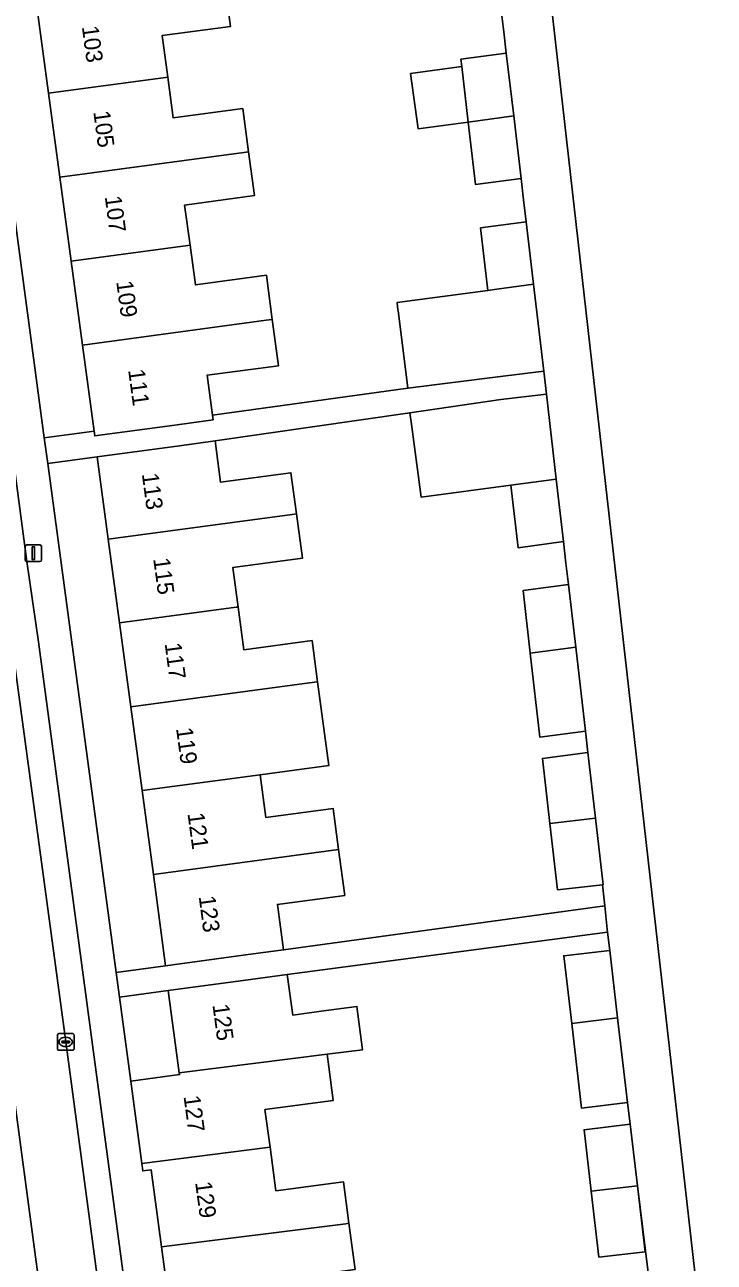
# Model space of a CAD drawing. Extents: x 163147 to 163550, y 380933 to 381639.
# Drawn here: x 163508.4 to 163549.9, y 381142.9 to 381217.3 of the extents above; entities that cross this region are included whole.
import ezdxf

# ---------------------------------------------------------------- set-up
doc = ezdxf.new("R2010")
doc.units = 0
for name, color, linetype in [('IMGEO_Erf', 7, 'Continuous'), ('IMGEO_Kolk', 7, 'Continuous'), ('IMGEO_Lichtmast', 7, 'Continuous'), ('IMGEO_Pand', 7, 'Continuous'), ('IMGEO_Pand_nummerreeks', 7, 'Continuous'), ('IMGEO_Parkeervlak_open', 7, 'Continuous'), ('IMGEO_Rijbaan_lokaal_open', 7, 'Continuous'), ('IMGEO_Voetpad_open', 7, 'Continuous')]:
    doc.layers.add(name, color=color, linetype=linetype)

msp = doc.modelspace()

# ---------------------------------------------------------------- linework, layer by layer
at = {"layer": 'IMGEO_Erf'}
for points in [[(163509.837, 381213.166), (163509.156, 381218.215), (163508.481, 381223.221), (163505.501, 381222.821), (163509.584, 381192.438), (163512.578, 381192.84), (163511.88, 381198.018), (163511.199, 381203.067), (163510.518, 381208.118)], [(163538.808, 381179.487), (163538.372, 381183.255), (163541.103, 381183.62), (163540.955, 381184.902), (163540.805, 381186.2), (163538.074, 381185.835), (163537.64, 381189.595), (163532.254, 381188.873), (163531.647, 381193.406), (163531.613, 381193.661), (163531.573, 381193.955), (163519.853, 381192.255), (163520.187, 381189.773), (163524.411, 381190.341), (163524.744, 381187.867), (163525.102, 381185.202), (163520.915, 381184.639), (163521.234, 381182.265), (163521.58, 381179.696), (163525.684, 381180.248), (163526.017, 381177.774), (163526.694, 381172.735), (163522.559, 381172.179), (163522.904, 381169.614), (163526.948, 381170.157), (163527.281, 381167.679), (163527.652, 381164.926), (163523.606, 381164.381), (163523.974, 381161.65), (163543.281, 381164.294), (163543.148, 381165.564), (163540.453, 381165.253), (163539.991, 381169.249), (163539.54, 381173.152), (163542.27, 381173.518), (163542.122, 381174.799), (163539.392, 381174.433)], [(163514.787, 381176.271), (163514.109, 381181.312), (163513.431, 381186.352), (163512.765, 381191.302), (163509.79, 381190.902), (163513.902, 381160.296), (163516.882, 381160.696), (163516.143, 381166.188), (163515.465, 381171.229)], [(163517.036, 381159.196), (163514.103, 381158.802), (163514.782, 381153.75), (163517.716, 381154.144), (163517.7, 381154.26)]]:
    msp.add_lwpolyline(points, close=True, dxfattribs=at)
for points in [[(163520.445, 381219.741), (163520.789, 381217.19), (163516.668, 381216.634), (163517.005, 381214.135), (163517.337, 381211.678), (163521.516, 381212.241), (163521.865, 381209.651), (163522.222, 381207.008), (163518.021, 381206.442), (163518.346, 381204.034), (163518.668, 381201.643), (163522.936, 381202.219), (163523.295, 381199.561), (163523.67, 381196.782), (163519.371, 381196.202), (163519.695, 381193.797), (163531.445, 381195.429), (163530.877, 381199.938), (163530.828, 381200.329), (163530.797, 381200.575), (163536.256, 381201.313), (163535.818, 381205.07), (163538.558, 381205.441), (163538.404, 381206.748), (163538.252, 381208.042), (163535.514, 381207.671), (163535.075, 381211.436), (163532.062, 381211.028), (163531.612, 381214.354), (163534.686, 381214.77), (163534.635, 381215.209), (163537.365, 381215.579), (163537.213, 381216.868), (163537.063, 381218.145)], [(163545.895, 381142.238), (163545.254, 381147.457), (163545.717, 381143.486), (163542.939, 381143.162), (163542.476, 381147.133), (163542.045, 381150.828), (163544.815, 381151.177), (163544.662, 381152.474), (163541.894, 381152.126), (163541.3, 381157.22), (163540.824, 381161.297), (163543.582, 381161.618), (163543.453, 381162.715), (163524.194, 381160.159), (163524.521, 381157.725), (163526.242, 381157.957), (163528.378, 381158.245), (163528.728, 381155.643), (163526.589, 381155.375), (163526.692, 381154.612), (163526.963, 381152.596), (163522.854, 381152.043), (163523.159, 381149.777), (163523.511, 381147.159), (163527.567, 381147.704), (163527.903, 381145.205), (163528.276, 381142.433)]]:
    msp.add_lwpolyline(points, dxfattribs=at)
at = {"layer": 'IMGEO_Kolk'}
for p, q in [((163510.371, 381155.684), (163510.371, 381156.536)), ((163510.446, 381156.61), (163511.298, 381156.61)), ((163510.63, 381156.104), (163510.63, 381156.116)), ((163511.068, 381156.067), (163510.67, 381156.067)), ((163510.673, 381156.153), (163511.071, 381156.153)), ((163510.859, 381156.39), (163510.884, 381156.39)), ((163511.114, 381156.116), (163511.114, 381156.104)), ((163511.372, 381156.536), (163511.372, 381155.684)), ((163511.298, 381155.61), (163510.446, 381155.61)), ((163510.882, 381155.83), (163510.857, 381155.83))]:
    msp.add_line(p, q, dxfattribs=at)
for points in [[(163510.371, 381155.684), (163510.371, 381156.536)], [(163510.446, 381156.61), (163511.298, 381156.61)], [(163511.372, 381156.536), (163511.372, 381155.684)], [(163511.298, 381155.61), (163510.446, 381155.61)]]:
    msp.add_lwpolyline(points, dxfattribs=at)
for centre, radius, start, end in [((163510.448, 381156.534), 0.0765, 91.55205, 178.44795), ((163510.448, 381156.534), 0.0765, 91.55205, 178.44795), ((163510.67, 381156.113), 0.0403, 85.87752, 175.75265), ((163510.667, 381156.103), 0.0366, 178.93798, 274.71019), ((163511.071, 381156.11), 0.043, 264.86636, 352.45326), ((163511.075, 381156.115), 0.0386, 1.73085, 96.63898), ((163511.296, 381156.534), 0.0765, 1.55205, 88.44795), ((163511.296, 381156.534), 0.0765, 1.55205, 88.44795), ((163510.448, 381155.686), 0.0765, 181.55205, 268.44795), ((163510.448, 381155.686), 0.0765, 181.55205, 268.44795), ((163511.296, 381155.686), 0.0765, 271.55205, 358.44795), ((163511.296, 381155.686), 0.0765, 271.55205, 358.44795)]:
    msp.add_arc(centre, radius, start, end, dxfattribs=at)
for centre, major_axis, ratio, start_param, end_param in [((163510.858, 381156.11), (-0.387, 0.002), 0.722429, 4.712389, 7.853982), ((163510.883, 381156.11), (-0.39, 0.002), 0.717154, 1.570796, 4.712389)]:
    msp.add_ellipse(centre, major_axis=major_axis, ratio=ratio, start_param=start_param, end_param=end_param, dxfattribs=at)
at = {"layer": 'IMGEO_Lichtmast'}
for p, q in [((163508.428, 381185.106), (163508.428, 381185.906)), ((163508.428, 381185.906), (163508.428, 381185.106)), ((163508.528, 381186.006), (163509.318, 381186.006)), ((163509.318, 381186.006), (163508.528, 381186.006)), ((163509.418, 381185.906), (163509.418, 381185.106)), ((163509.418, 381185.106), (163509.418, 381185.906)), ((163509.318, 381185.006), (163508.528, 381185.006)), ((163508.528, 381185.006), (163509.318, 381185.006))]:
    msp.add_line(p, q, dxfattribs=at)
msp.add_lwpolyline([(163508.848, 381185.881), (163508.998, 381185.881), (163508.998, 381185.131), (163508.848, 381185.131), (163508.848, 381185.881)], dxfattribs=at)
for centre, start, end in [((163508.528, 381185.906), 90, 180), ((163508.528, 381185.906), 90, 180), ((163509.318, 381185.906), 0, 90), ((163509.318, 381185.906), 360, 90), ((163508.528, 381185.106), 180, 270), ((163508.528, 381185.106), 180, 270), ((163509.318, 381185.106), 270, 0), ((163509.318, 381185.106), 270, 0)]:
    msp.add_arc(centre, 0.1, start, end, dxfattribs=at)
at = {"layer": 'IMGEO_Pand'}
for points in [[(163517.005, 381214.135), (163516.668, 381216.634), (163520.789, 381217.19), (163520.445, 381219.741), (163520.224, 381219.711), (163509.156, 381218.215), (163509.837, 381213.166), (163516.87, 381214.117)], [(163537.365, 381215.579), (163534.635, 381215.209), (163534.686, 381214.77), (163535.075, 381211.436), (163537.809, 381211.805)], [(163534.686, 381214.77), (163531.612, 381214.354), (163532.062, 381211.028), (163535.075, 381211.436)], [(163510.518, 381208.118), (163521.575, 381209.612), (163521.865, 381209.651), (163521.516, 381212.241), (163517.337, 381211.678), (163517.005, 381214.135), (163516.87, 381214.117), (163509.837, 381213.166)], [(163537.809, 381211.805), (163535.075, 381211.436), (163535.514, 381207.671), (163538.252, 381208.042)], [(163510.518, 381208.118), (163511.199, 381203.067), (163518.221, 381204.017), (163518.346, 381204.034), (163518.021, 381206.442), (163522.222, 381207.008), (163521.865, 381209.651), (163521.575, 381209.612)], [(163538.558, 381205.441), (163535.818, 381205.07), (163536.256, 381201.313), (163536.8, 381201.387), (163539, 381201.684)], [(163511.88, 381198.018), (163522.925, 381199.511), (163523.295, 381199.561), (163522.936, 381202.219), (163518.668, 381201.643), (163518.346, 381204.034), (163518.221, 381204.017), (163511.199, 381203.067)], [(163539, 381201.684), (163536.8, 381201.387), (163536.256, 381201.313), (163530.797, 381200.575), (163530.828, 381200.329), (163530.877, 381199.938), (163531.445, 381195.429), (163536.862, 381196.112), (163539.615, 381196.459)], [(163519.371, 381196.202), (163523.67, 381196.782), (163523.295, 381199.561), (163522.925, 381199.511), (163511.88, 381198.018), (163512.578, 381192.84), (163512.616, 381192.558), (163517.572, 381193.227), (163519.733, 381193.518), (163519.695, 381193.797)], [(163539.78, 381195.068), (163537.044, 381194.749), (163531.573, 381193.955), (163531.613, 381193.661), (163531.647, 381193.406), (163532.254, 381188.873), (163537.64, 381189.595), (163540.37, 381189.961)], [(163524.744, 381187.867), (163524.411, 381190.341), (163520.187, 381189.773), (163519.853, 381192.255), (163517.721, 381191.968), (163512.765, 381191.302), (163513.431, 381186.352), (163524.487, 381187.833)], [(163540.37, 381189.961), (163537.64, 381189.595), (163538.074, 381185.835), (163540.805, 381186.2)], [(163521.234, 381182.265), (163520.915, 381184.639), (163525.102, 381185.202), (163524.744, 381187.867), (163524.487, 381187.833), (163513.431, 381186.352), (163514.109, 381181.312), (163521.131, 381182.251)], [(163541.103, 381183.62), (163538.372, 381183.255), (163538.808, 381179.487), (163541.538, 381179.852)], [(163521.234, 381182.265), (163521.131, 381182.251), (163514.109, 381181.312), (163514.787, 381176.271), (163525.835, 381177.75), (163526.017, 381177.774), (163525.684, 381180.248), (163521.58, 381179.696)], [(163538.808, 381179.487), (163539.392, 381174.433), (163542.122, 381174.799), (163541.538, 381179.852)], [(163526.017, 381177.774), (163525.835, 381177.75), (163514.787, 381176.271), (163515.465, 381171.229), (163522.559, 381172.179), (163526.694, 381172.735)], [(163542.27, 381173.518), (163539.54, 381173.152), (163539.991, 381169.249), (163542.727, 381169.568)], [(163522.559, 381172.179), (163515.465, 381171.229), (163516.143, 381166.188), (163527.281, 381167.679), (163526.948, 381170.157), (163522.904, 381169.614)], [(163542.727, 381169.568), (163539.991, 381169.249), (163540.453, 381165.253), (163543.148, 381165.564), (163543.189, 381165.569)], [(163527.281, 381167.679), (163516.143, 381166.188), (163516.882, 381160.696), (163521.838, 381161.363), (163523.974, 381161.65), (163523.606, 381164.381), (163527.652, 381164.926)], [(163543.582, 381161.618), (163540.824, 381161.297), (163541.3, 381157.22), (163544.061, 381157.566)], [(163524.194, 381160.159), (163521.992, 381159.863), (163517.036, 381159.196), (163517.7, 381154.26), (163526.589, 381155.375), (163528.728, 381155.643), (163528.378, 381158.245), (163526.242, 381157.957), (163524.521, 381157.725)], [(163544.061, 381157.566), (163541.3, 381157.22), (163541.894, 381152.126), (163544.662, 381152.474)], [(163526.692, 381154.612), (163526.589, 381155.375), (163517.7, 381154.26), (163517.716, 381154.144), (163514.782, 381153.75), (163515.446, 381148.81), (163523.014, 381149.759), (163523.159, 381149.777), (163522.854, 381152.043), (163526.963, 381152.596)], [(163544.815, 381151.177), (163542.045, 381150.828), (163542.476, 381147.133), (163545.254, 381147.457)], [(163515.446, 381148.81), (163515.507, 381148.36), (163516.006, 381148.427), (163516.63, 381143.791), (163527.724, 381145.183), (163527.903, 381145.205), (163527.567, 381147.704), (163523.511, 381147.159), (163523.159, 381149.777), (163523.014, 381149.759)], [(163545.254, 381147.457), (163542.476, 381147.133), (163542.939, 381143.162), (163545.717, 381143.486)], [(163517.313, 381138.711), (163524.359, 381139.594), (163524.515, 381139.614), (163524.21, 381141.886), (163528.276, 381142.433), (163527.903, 381145.205), (163527.724, 381145.183), (163516.63, 381143.791)]]:
    msp.add_lwpolyline(points, close=True, dxfattribs=at)
at = {"layer": 'IMGEO_Parkeervlak_open'}
for points in [[(163503.796, 381208.674), (163504.806, 381200.993), (163506.998, 381184.771), (163507.648, 381179.955), (163510.87, 381156.109), (163513.587, 381135.867), (163514.789, 381126.831), (163514.8, 381126.75), (163516.355, 381126.983)], [(163516.355, 381126.983), (163516.345, 381127.061), (163509.233, 381180.183), (163508.536, 381185.012), (163505.712, 381206.244)], [(163513.15, 381112.822), (163512.657, 381116.312), (163510.084, 381135.559), (163507.418, 381155.47)]]:
    msp.add_lwpolyline(points, dxfattribs=at)
at = {"layer": 'IMGEO_Rijbaan_lokaal_open'}
for points in [[(163549.87, 381132.002), (163529.08, 381315.546)], [(163537.063, 381218.145), (163537.213, 381216.868), (163537.365, 381215.579), (163537.809, 381211.805), (163538.252, 381208.042), (163538.404, 381206.748), (163538.558, 381205.441), (163539, 381201.684), (163539.615, 381196.459), (163539.78, 381195.068), (163540.37, 381189.961), (163540.805, 381186.2), (163540.955, 381184.902), (163541.103, 381183.62), (163541.538, 381179.852), (163542.122, 381174.799), (163542.27, 381173.518), (163542.727, 381169.568), (163543.189, 381165.569), (163543.148, 381165.564), (163543.281, 381164.294), (163543.432, 381162.89), (163543.453, 381162.715), (163543.582, 381161.618), (163544.061, 381157.566), (163544.662, 381152.474), (163544.815, 381151.177), (163545.254, 381147.457), (163545.895, 381142.238)]]:
    msp.add_lwpolyline(points, dxfattribs=at)
msp.add_lwpolyline([(163514.8, 381126.75), (163514.789, 381126.831), (163513.587, 381135.867), (163510.87, 381156.109), (163507.648, 381179.955), (163504.184, 381179.487), (163504.439, 381177.585), (163507.418, 381155.47), (163510.084, 381135.559), (163512.657, 381116.312), (163513.15, 381112.822), (163513.165, 381112.719), (163513.181, 381112.606), (163513.54, 381109.521), (163515.019, 381109.754), (163516.743, 381110.026), (163514.166, 381126.655)], close=True, dxfattribs=at)
at = {"layer": 'IMGEO_Voetpad_open'}
for points in [[(163518.312, 381127.276), (163518.295, 381127.348), (163518.211, 381127.971), (163517.529, 381133.05), (163517.46, 381133.562), (163516.787, 381138.564), (163517.313, 381138.711), (163516.63, 381143.791), (163516.006, 381148.427), (163515.507, 381148.36), (163515.446, 381148.81), (163514.782, 381153.75), (163514.103, 381158.802), (163513.902, 381160.296), (163509.79, 381190.902), (163509.584, 381192.438), (163505.501, 381222.821)], [(163505.712, 381206.244), (163508.536, 381185.012), (163509.233, 381180.183), (163516.345, 381127.061), (163516.355, 381126.983), (163518.312, 381127.276)]]:
    msp.add_lwpolyline(points, dxfattribs=at)
for points in [[(163531.573, 381193.955), (163537.044, 381194.749), (163539.78, 381195.068), (163539.615, 381196.459), (163536.862, 381196.112), (163531.445, 381195.429), (163519.695, 381193.797), (163519.733, 381193.518), (163517.572, 381193.227), (163512.616, 381192.558), (163512.578, 381192.84), (163509.584, 381192.438), (163509.79, 381190.902), (163512.765, 381191.302), (163517.721, 381191.968), (163519.853, 381192.255)], [(163543.453, 381162.715), (163543.432, 381162.89), (163543.281, 381164.294), (163523.974, 381161.65), (163521.838, 381161.363), (163516.882, 381160.696), (163513.902, 381160.296), (163514.103, 381158.802), (163517.036, 381159.196), (163521.992, 381159.863), (163524.194, 381160.159)]]:
    msp.add_lwpolyline(points, close=True, dxfattribs=at)

# ---------------------------------------------------------------- texts
at = {"layer": 'IMGEO_Pand_nummerreeks'}
for s, rotation, p in [('103', 277.68018, (163511.84, 381217.168)), ('105', 277.68018, (163512.529, 381212.057)), ('107', 277.68018, (163513.218, 381206.947)), ('109', 277.68018, (163513.907, 381201.836)), ('111', 277.67742, (163514.624, 381196.523)), ('113', 277.66122, (163515.446, 381190.272)), ('115', 277.66122, (163516.132, 381185.171)), ('117', 277.66122, (163516.819, 381180.07)), ('119', 277.66024, (163517.505, 381174.969)), ('121', 277.66122, (163518.194, 381169.846)), ('123', 277.66122, (163518.865, 381164.858)), ('125', 277.66596, (163519.694, 381158.34)), ('127', 277.66024, (163517.955, 381152.842)), ('129', 277.66095, (163518.651, 381147.668))]:
    msp.add_text(s, height=1, rotation=rotation, dxfattribs=at).set_placement(p)

doc.saveas('drawing.dxf')
